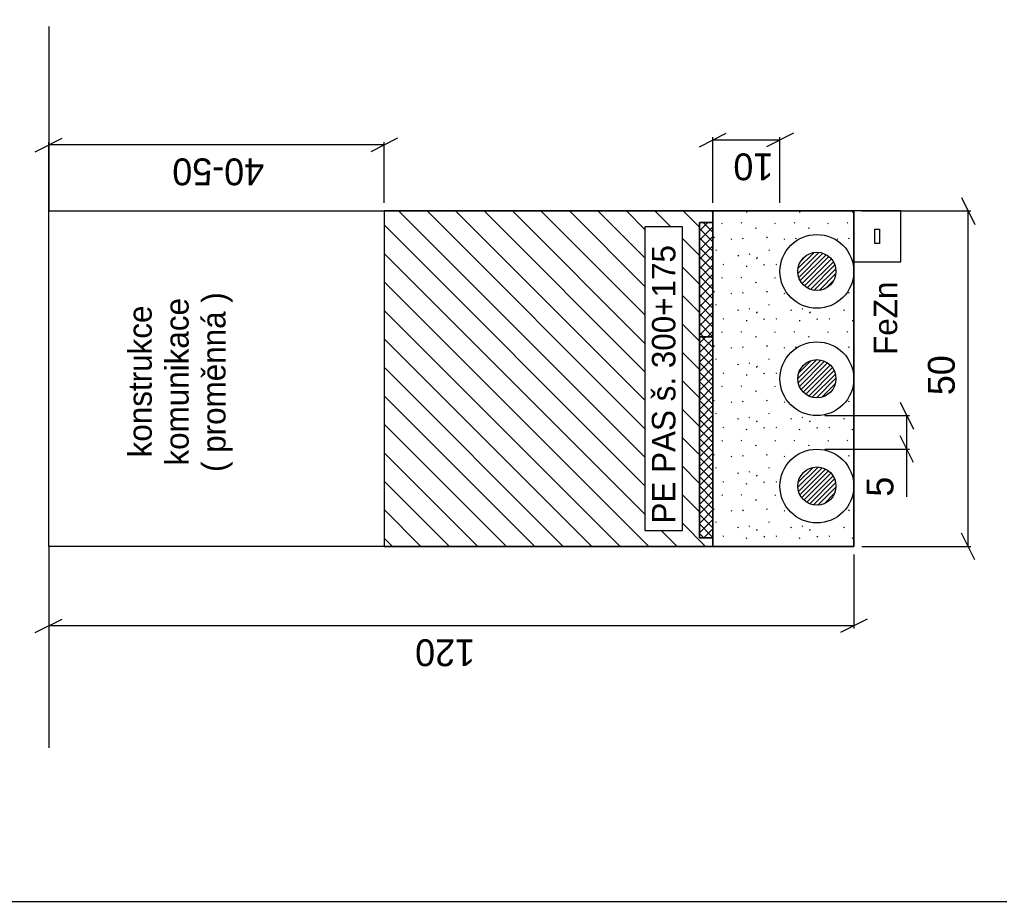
# Model space of a CAD drawing. Extents: x -762592 to -762444, y -1032635 to -1032425.
# Drawn here: x -762577.86 to -762554.5, y -1032634.69 to -1032613.66 of the extents above; entities that cross this region are included whole.
import ezdxf

# ---------------------------------------------------------------- set-up
doc = ezdxf.new("R2010")
doc.units = 0
for name, color, linetype in [('Kabeláž - kabelové vedení HDV - stávající', 7, 'Continuous'), ('Tisk', 7, 'Continuous'), ('X ŘEZY TRASOU', 7, 'Continuous'), ('X ŘEZY TRASOU - KÓTY', 7, 'Continuous'), ('X ŘEZY TRASOU - ŠRAFY', 7, 'Continuous')]:
    doc.layers.add(name, color=color, linetype=linetype)

msp = doc.modelspace()

# ---------------------------------------------------------------- linework, layer by layer
at = {"layer": 'Kabeláž - kabelové vedení HDV - stávající'}
for p, q in [((-762559.301, -1032619.71), (-762558.799, -1032619.208)), ((-762559.299, -1032619.596), (-762558.913, -1032619.21)), ((-762559.281, -1032619.803), (-762558.705, -1032619.228)), ((-762559.246, -1032619.882), (-762558.627, -1032619.263)), ((-762559.231, -1032619.414), (-762559.095, -1032619.278)), ((-762559.201, -1032619.95), (-762558.56, -1032619.309)), ((-762559.145, -1032620.006), (-762558.502, -1032619.364)), ((-762559.079, -1032620.054), (-762558.456, -1032619.431)), ((-762559.002, -1032620.09), (-762558.42, -1032619.508)), ((-762558.91, -1032620.112), (-762558.398, -1032619.599)), ((-762558.798, -1032620.113), (-762558.396, -1032619.711)), ((-762558.635, -1032620.062), (-762558.446, -1032619.873)), ((-762559.304, -1032622.216), (-762558.853, -1032621.765)), ((-762559.293, -1032622.319), (-762558.751, -1032621.776)), ((-762559.282, -1032622.081), (-762558.988, -1032621.788)), ((-762559.266, -1032622.405), (-762558.665, -1032621.804)), ((-762559.225, -1032622.477), (-762558.592, -1032621.844)), ((-762559.174, -1032622.539), (-762558.53, -1032621.895)), ((-762559.114, -1032622.592), (-762558.478, -1032621.956)), ((-762559.042, -1032622.633), (-762558.436, -1032622.027)), ((-762558.958, -1032622.663), (-762558.407, -1032622.111)), ((-762558.858, -1032622.676), (-762558.394, -1032622.211)), ((-762558.729, -1032622.66), (-762558.41, -1032622.34)), ((-762559.303, -1032624.81), (-762558.819, -1032624.326)), ((-762559.294, -1032624.688), (-762558.941, -1032624.335)), ((-762559.287, -1032624.907), (-762558.723, -1032624.343)), ((-762559.254, -1032624.988), (-762558.641, -1032624.375)), ((-762559.21, -1032625.057), (-762558.572, -1032624.419)), ((-762559.157, -1032625.116), (-762558.513, -1032624.473)), ((-762559.092, -1032625.165), (-762558.464, -1032624.537)), ((-762559.018, -1032625.204), (-762558.426, -1032624.612)), ((-762558.929, -1032625.229), (-762558.4, -1032624.699)), ((-762558.823, -1032625.235), (-762558.394, -1032624.806)), ((-762558.676, -1032625.202), (-762558.427, -1032624.953))]:
    msp.add_line(p, q, dxfattribs=at)
at = {"layer": 'Tisk'}
msp.add_lwpolyline([(-762589.528, -1032529.685), (-762592.028, -1032529.685), (-762592.028, -1032634.685), (-762443.528, -1032634.685), (-762443.528, -1032529.685), (-762446.028, -1032529.685)], dxfattribs=at)
at = {"layer": 'X ŘEZY TRASOU'}
for p, q in [((-762577.169, -1032613.821), (-762577.169, -1032618.221)), ((-762577.169, -1032626.221), (-762577.169, -1032618.221)), ((-762577.169, -1032618.221), (-762561.329, -1032618.221)), ((-762569.169, -1032618.221), (-762569.169, -1032626.221)), ((-762561.329, -1032618.221), (-762561.329, -1032626.221)), ((-762561.329, -1032626.221), (-762561.329, -1032618.221)), ((-762561.329, -1032618.221), (-762557.969, -1032618.221)), ((-762557.969, -1032618.221), (-762557.969, -1032619.43)), ((-762556.847, -1032618.221), (-762557.969, -1032618.221)), ((-762557.969, -1032618.221), (-762557.969, -1032626.221)), ((-762556.847, -1032619.43), (-762556.847, -1032618.221)), ((-762561.329, -1032618.498), (-762561.649, -1032618.498)), ((-762561.649, -1032618.498), (-762561.649, -1032621.218)), ((-762561.649, -1032618.694), (-762561.453, -1032618.498)), ((-762561.329, -1032618.498), (-762561.649, -1032618.498)), ((-762561.649, -1032618.498), (-762561.649, -1032621.218)), ((-762561.649, -1032618.92), (-762561.329, -1032618.6)), ((-762561.329, -1032618.729), (-762561.56, -1032618.498)), ((-762561.329, -1032618.502), (-762561.334, -1032618.498)), ((-762561.329, -1032621.218), (-762561.329, -1032618.498)), ((-762561.329, -1032621.218), (-762561.329, -1032618.498)), ((-762561.329, -1032618.955), (-762561.649, -1032618.635)), ((-762561.649, -1032619.146), (-762561.329, -1032618.826)), ((-762557.463, -1032618.997), (-762557.463, -1032618.654)), ((-762557.463, -1032618.654), (-762557.352, -1032618.654)), ((-762557.352, -1032618.654), (-762557.352, -1032618.997)), ((-762561.329, -1032619.181), (-762561.649, -1032618.861)), ((-762561.649, -1032619.373), (-762561.329, -1032619.053)), ((-762557.352, -1032618.997), (-762557.463, -1032618.997)), ((-762561.329, -1032619.408), (-762561.649, -1032619.088)), ((-762561.649, -1032619.599), (-762561.329, -1032619.279)), ((-762561.329, -1032619.634), (-762561.649, -1032619.314)), ((-762561.649, -1032619.825), (-762561.329, -1032619.505)), ((-762561.329, -1032619.86), (-762561.649, -1032619.54)), ((-762557.969, -1032619.43), (-762556.847, -1032619.43)), ((-762561.649, -1032620.051), (-762561.329, -1032619.731)), ((-762561.329, -1032620.086), (-762561.649, -1032619.766)), ((-762561.649, -1032620.278), (-762561.329, -1032619.958)), ((-762561.329, -1032620.313), (-762561.649, -1032619.993)), ((-762561.649, -1032620.504), (-762561.329, -1032620.184)), ((-762561.329, -1032620.539), (-762561.649, -1032620.219)), ((-762561.649, -1032620.73), (-762561.329, -1032620.41)), ((-762561.329, -1032620.765), (-762561.649, -1032620.445)), ((-762561.649, -1032620.956), (-762561.329, -1032620.636)), ((-762561.329, -1032620.992), (-762561.649, -1032620.672)), ((-762561.649, -1032621.183), (-762561.329, -1032620.863)), ((-762561.329, -1032621.218), (-762561.649, -1032620.898)), ((-762561.555, -1032621.218), (-762561.649, -1032621.124)), ((-762561.457, -1032621.218), (-762561.329, -1032621.089)), ((-762561.649, -1032626.018), (-762561.649, -1032621.218)), ((-762561.649, -1032621.218), (-762561.329, -1032621.218)), ((-762561.649, -1032621.372), (-762561.495, -1032621.218)), ((-762561.649, -1032621.218), (-762561.329, -1032621.218)), ((-762561.329, -1032621.218), (-762561.649, -1032621.218)), ((-762561.649, -1032621.218), (-762561.649, -1032626.018)), ((-762561.649, -1032621.218), (-762561.329, -1032621.218)), ((-762561.649, -1032621.598), (-762561.329, -1032621.278)), ((-762561.329, -1032621.704), (-762561.649, -1032621.384)), ((-762561.329, -1032621.478), (-762561.589, -1032621.218)), ((-762561.329, -1032621.252), (-762561.363, -1032621.218)), ((-762561.329, -1032621.218), (-762561.329, -1032626.018)), ((-762561.329, -1032626.018), (-762561.329, -1032621.218)), ((-762561.649, -1032621.824), (-762561.329, -1032621.504)), ((-762561.329, -1032621.931), (-762561.649, -1032621.611)), ((-762561.649, -1032622.051), (-762561.329, -1032621.731)), ((-762561.329, -1032622.157), (-762561.649, -1032621.837)), ((-762561.649, -1032622.277), (-762561.329, -1032621.957)), ((-762561.329, -1032622.383), (-762561.649, -1032622.063)), ((-762561.649, -1032622.503), (-762561.329, -1032622.183)), ((-762561.329, -1032622.61), (-762561.649, -1032622.29)), ((-762561.649, -1032622.729), (-762561.329, -1032622.409)), ((-762561.329, -1032622.836), (-762561.649, -1032622.516)), ((-762561.649, -1032622.956), (-762561.329, -1032622.636)), ((-762561.329, -1032623.062), (-762561.649, -1032622.742)), ((-762561.649, -1032623.182), (-762561.329, -1032622.862)), ((-762561.329, -1032623.288), (-762561.649, -1032622.968)), ((-762561.649, -1032623.408), (-762561.329, -1032623.088)), ((-762561.329, -1032623.515), (-762561.649, -1032623.195)), ((-762561.649, -1032623.634), (-762561.329, -1032623.314)), ((-762561.329, -1032623.741), (-762561.649, -1032623.421)), ((-762561.649, -1032623.861), (-762561.329, -1032623.541)), ((-762561.329, -1032623.967), (-762561.649, -1032623.647)), ((-762561.649, -1032624.087), (-762561.329, -1032623.767)), ((-762561.329, -1032624.193), (-762561.649, -1032623.873)), ((-762561.649, -1032624.313), (-762561.329, -1032623.993)), ((-762561.329, -1032624.42), (-762561.649, -1032624.1)), ((-762561.649, -1032624.54), (-762561.329, -1032624.22)), ((-762561.329, -1032624.646), (-762561.649, -1032624.326)), ((-762561.649, -1032624.766), (-762561.329, -1032624.446)), ((-762561.329, -1032624.872), (-762561.649, -1032624.552)), ((-762561.649, -1032624.992), (-762561.329, -1032624.672)), ((-762561.329, -1032625.099), (-762561.649, -1032624.779)), ((-762561.649, -1032625.218), (-762561.329, -1032624.898)), ((-762561.329, -1032625.325), (-762561.649, -1032625.005)), ((-762561.649, -1032625.445), (-762561.329, -1032625.125)), ((-762561.329, -1032625.551), (-762561.649, -1032625.231)), ((-762561.649, -1032625.671), (-762561.329, -1032625.351)), ((-762561.329, -1032625.777), (-762561.649, -1032625.457)), ((-762561.649, -1032625.897), (-762561.329, -1032625.577)), ((-762561.329, -1032626.004), (-762561.649, -1032625.684)), ((-762561.543, -1032626.018), (-762561.329, -1032625.804)), ((-762561.541, -1032626.018), (-762561.649, -1032625.91)), ((-762561.329, -1032626.018), (-762561.649, -1032626.018)), ((-762561.649, -1032626.018), (-762561.329, -1032626.018)), ((-762577.169, -1032626.221), (-762577.169, -1032631.021)), ((-762561.329, -1032626.221), (-762577.169, -1032626.221)), ((-762557.969, -1032626.221), (-762561.329, -1032626.221)), ((-762577.169, -1032627.821), (-762577.169, -1032630.115))]:
    msp.add_line(p, q, dxfattribs=at)
for centre, radius in [((-762558.849, -1032619.661), 0.88), ((-762558.849, -1032619.661), 0.456), ((-762558.849, -1032622.221), 0.88), ((-762558.849, -1032622.221), 0.456), ((-762558.849, -1032624.781), 0.88), ((-762558.849, -1032624.781), 0.456)]:
    msp.add_circle(centre, radius, dxfattribs=at)
at = {"layer": 'X ŘEZY TRASOU - KÓTY'}
for p, q in [((-762577.489, -1032616.807), (-762576.849, -1032616.487)), ((-762568.849, -1032616.487), (-762569.489, -1032616.807)), ((-762561.649, -1032616.687), (-762561.009, -1032616.367)), ((-762561.329, -1032618.029), (-762561.329, -1032616.463)), ((-762559.409, -1032616.367), (-762560.049, -1032616.687)), ((-762559.729, -1032618.029), (-762559.729, -1032616.463)), ((-762577.169, -1032618.221), (-762577.169, -1032616.583)), ((-762569.169, -1032616.647), (-762577.169, -1032616.647)), ((-762569.169, -1032618.029), (-762569.169, -1032616.583)), ((-762561.329, -1032616.527), (-762559.729, -1032616.527)), ((-762555.401, -1032617.901), (-762555.081, -1032618.541)), ((-762557.777, -1032618.221), (-762555.177, -1032618.221)), ((-762555.241, -1032626.221), (-762555.241, -1032618.221)), ((-762556.864, -1032622.781), (-762556.544, -1032623.421)), ((-762558.657, -1032623.101), (-762556.64, -1032623.101)), ((-762556.704, -1032623.901), (-762556.704, -1032623.101)), ((-762556.544, -1032624.221), (-762556.864, -1032623.581)), ((-762558.657, -1032623.901), (-762556.64, -1032623.901)), ((-762556.704, -1032625.034), (-762556.704, -1032623.901)), ((-762555.081, -1032626.541), (-762555.401, -1032625.901)), ((-762557.777, -1032626.221), (-762555.177, -1032626.221)), ((-762577.169, -1032626.413), (-762577.169, -1032628.179)), ((-762557.969, -1032626.413), (-762557.969, -1032628.179)), ((-762577.489, -1032628.275), (-762576.849, -1032627.955)), ((-762557.649, -1032627.955), (-762558.289, -1032628.275)), ((-762557.969, -1032628.115), (-762577.169, -1032628.115))]:
    msp.add_line(p, q, dxfattribs=at)
at = {"layer": 'X ŘEZY TRASOU - ŠRAFY'}
for p, q in [((-762569.169, -1032618.221), (-762569.169, -1032626.221)), ((-762562.951, -1032624.093), (-762568.824, -1032618.221)), ((-762562.951, -1032623.414), (-762568.145, -1032618.221)), ((-762562.951, -1032622.735), (-762567.466, -1032618.221)), ((-762562.951, -1032622.056), (-762566.787, -1032618.221)), ((-762562.951, -1032621.378), (-762566.108, -1032618.221)), ((-762562.951, -1032620.699), (-762565.429, -1032618.221)), ((-762562.951, -1032620.02), (-762564.751, -1032618.221)), ((-762562.951, -1032619.341), (-762564.072, -1032618.221)), ((-762562.951, -1032618.662), (-762563.393, -1032618.221)), ((-762562.335, -1032618.6), (-762562.714, -1032618.221)), ((-762561.649, -1032618.607), (-762562.035, -1032618.221)), ((-762561.329, -1032618.249), (-762561.357, -1032618.221)), ((-762557.969, -1032618.221), (-762561.329, -1032618.221)), ((-762561.329, -1032618.221), (-762561.329, -1032618.498)), ((-762560.533, -1032618.241), (-762560.509, -1032618.239)), ((-762559.269, -1032618.241), (-762559.244, -1032618.239)), ((-762558.004, -1032618.241), (-762557.98, -1032618.239)), ((-762557.969, -1032619.43), (-762557.969, -1032618.221)), ((-762562.951, -1032624.772), (-762569.169, -1032618.554)), ((-762562.055, -1032618.6), (-762562.951, -1032618.6)), ((-762562.951, -1032618.6), (-762562.951, -1032625.842)), ((-762562.055, -1032625.842), (-762562.055, -1032618.6)), ((-762561.649, -1032621.218), (-762561.649, -1032618.498)), ((-762561.649, -1032618.498), (-762561.329, -1032618.498)), ((-762561.329, -1032618.498), (-762561.329, -1032621.218)), ((-762561.115, -1032618.52), (-762561.099, -1032618.509)), ((-762560.653, -1032618.509), (-762560.637, -1032618.499)), ((-762559.851, -1032618.52), (-762559.835, -1032618.509)), ((-762559.389, -1032618.509), (-762559.373, -1032618.499)), ((-762558.587, -1032618.52), (-762558.57, -1032618.509)), ((-762558.125, -1032618.509), (-762558.108, -1032618.499)), ((-762561.288, -1032618.858), (-762561.313, -1032618.847)), ((-762560.287, -1032618.639), (-762560.311, -1032618.628)), ((-762560.024, -1032618.858), (-762560.048, -1032618.847)), ((-762559.023, -1032618.639), (-762559.047, -1032618.628)), ((-762561.649, -1032619.286), (-762562.055, -1032618.879)), ((-762560.894, -1032618.894), (-762560.877, -1032618.883)), ((-762560.601, -1032618.885), (-762560.625, -1032618.874)), ((-762559.629, -1032618.894), (-762559.613, -1032618.883)), ((-762559.337, -1032618.885), (-762559.361, -1032618.874)), ((-762558.365, -1032618.894), (-762558.349, -1032618.883)), ((-762558.072, -1032618.885), (-762558.097, -1032618.874)), ((-762562.951, -1032625.45), (-762569.169, -1032619.233)), ((-762561.257, -1032619.161), (-762561.241, -1032619.15)), ((-762560.712, -1032619.296), (-762560.736, -1032619.286)), ((-762560.461, -1032619.257), (-762560.445, -1032619.246)), ((-762559.992, -1032619.161), (-762559.976, -1032619.15)), ((-762561.086, -1032619.496), (-762561.07, -1032619.485)), ((-762560.533, -1032619.538), (-762560.509, -1032619.535)), ((-762560.287, -1032619.353), (-762560.271, -1032619.342)), ((-762560.281, -1032619.342), (-762560.265, -1032619.332)), ((-762560.086, -1032619.513), (-762560.111, -1032619.502)), ((-762559.822, -1032619.496), (-762559.805, -1032619.485)), ((-762557.969, -1032624.781), (-762557.969, -1032619.43)), ((-762561.649, -1032619.965), (-762562.055, -1032619.558)), ((-762562.86, -1032626.221), (-762569.169, -1032619.912)), ((-762561.115, -1032619.816), (-762561.099, -1032619.805)), ((-762560.653, -1032619.806), (-762560.637, -1032619.795)), ((-762560.287, -1032619.935), (-762560.311, -1032619.924)), ((-762559.851, -1032619.816), (-762559.835, -1032619.805)), ((-762561.649, -1032620.644), (-762562.055, -1032620.237)), ((-762561.288, -1032620.154), (-762561.313, -1032620.144)), ((-762560.894, -1032620.19), (-762560.877, -1032620.18)), ((-762560.601, -1032620.182), (-762560.625, -1032620.171)), ((-762560.024, -1032620.154), (-762560.048, -1032620.144)), ((-762559.629, -1032620.19), (-762559.613, -1032620.18)), ((-762558.072, -1032620.182), (-762558.097, -1032620.171)), ((-762561.257, -1032620.457), (-762561.241, -1032620.447)), ((-762559.992, -1032620.457), (-762559.976, -1032620.447)), ((-762563.539, -1032626.221), (-762569.169, -1032620.591)), ((-762560.712, -1032620.593), (-762560.736, -1032620.582)), ((-762560.461, -1032620.554), (-762560.445, -1032620.543)), ((-762560.287, -1032620.65), (-762560.271, -1032620.639)), ((-762560.281, -1032620.639), (-762560.265, -1032620.628)), ((-762559.448, -1032620.593), (-762559.472, -1032620.582)), ((-762559.197, -1032620.554), (-762559.181, -1032620.543)), ((-762559.023, -1032620.65), (-762559.006, -1032620.639)), ((-762559.016, -1032620.639), (-762559, -1032620.628)), ((-762558.183, -1032620.593), (-762558.208, -1032620.582)), ((-762561.649, -1032621.323), (-762562.055, -1032620.916)), ((-762561.086, -1032620.793), (-762561.07, -1032620.782)), ((-762560.533, -1032620.835), (-762560.509, -1032620.832)), ((-762560.086, -1032620.81), (-762560.111, -1032620.799)), ((-762559.822, -1032620.793), (-762559.805, -1032620.782)), ((-762559.269, -1032620.835), (-762559.244, -1032620.832)), ((-762558.822, -1032620.81), (-762558.846, -1032620.799)), ((-762558.557, -1032620.793), (-762558.541, -1032620.782)), ((-762558.004, -1032620.835), (-762557.98, -1032620.832)), ((-762561.115, -1032621.113), (-762561.099, -1032621.102)), ((-762560.653, -1032621.102), (-762560.637, -1032621.092)), ((-762559.851, -1032621.113), (-762559.835, -1032621.102)), ((-762559.389, -1032621.102), (-762559.373, -1032621.092)), ((-762558.587, -1032621.113), (-762558.57, -1032621.102)), ((-762558.125, -1032621.102), (-762558.108, -1032621.092)), ((-762564.218, -1032626.221), (-762569.169, -1032621.27)), ((-762561.329, -1032621.218), (-762561.329, -1032626.018)), ((-762560.287, -1032621.232), (-762560.311, -1032621.221)), ((-762559.023, -1032621.232), (-762559.047, -1032621.221)), ((-762561.649, -1032622.001), (-762562.055, -1032621.595)), ((-762561.288, -1032621.451), (-762561.313, -1032621.44)), ((-762560.894, -1032621.487), (-762560.877, -1032621.476)), ((-762560.601, -1032621.478), (-762560.625, -1032621.467)), ((-762560.024, -1032621.451), (-762560.048, -1032621.44)), ((-762559.629, -1032621.487), (-762559.613, -1032621.476)), ((-762559.337, -1032621.478), (-762559.361, -1032621.467)), ((-762558.364, -1032621.486), (-762558.349, -1032621.476)), ((-762558.072, -1032621.478), (-762558.097, -1032621.467)), ((-762561.257, -1032621.754), (-762561.241, -1032621.743)), ((-762560.712, -1032621.889), (-762560.736, -1032621.879)), ((-762560.461, -1032621.85), (-762560.445, -1032621.839)), ((-762559.992, -1032621.754), (-762559.976, -1032621.743)), ((-762564.896, -1032626.221), (-762569.169, -1032621.949)), ((-762561.086, -1032622.089), (-762561.07, -1032622.078)), ((-762560.287, -1032621.946), (-762560.271, -1032621.936)), ((-762560.281, -1032621.936), (-762560.265, -1032621.925)), ((-762560.086, -1032622.106), (-762560.111, -1032622.095)), ((-762559.822, -1032622.089), (-762559.805, -1032622.078)), ((-762561.649, -1032622.68), (-762562.055, -1032622.274)), ((-762560.533, -1032622.131), (-762560.509, -1032622.128)), ((-762561.115, -1032622.409), (-762561.099, -1032622.398)), ((-762560.653, -1032622.399), (-762560.637, -1032622.388)), ((-762560.287, -1032622.528), (-762560.311, -1032622.517)), ((-762559.851, -1032622.409), (-762559.835, -1032622.398)), ((-762565.575, -1032626.221), (-762569.169, -1032622.627)), ((-762561.288, -1032622.748), (-762561.313, -1032622.737)), ((-762560.894, -1032622.784), (-762560.877, -1032622.773)), ((-762560.601, -1032622.775), (-762560.625, -1032622.764)), ((-762560.024, -1032622.748), (-762560.048, -1032622.737)), ((-762559.629, -1032622.784), (-762559.613, -1032622.773)), ((-762558.072, -1032622.775), (-762558.097, -1032622.764)), ((-762561.649, -1032623.359), (-762562.055, -1032622.952)), ((-762561.257, -1032623.05), (-762561.241, -1032623.04)), ((-762559.992, -1032623.05), (-762559.976, -1032623.04)), ((-762560.712, -1032623.186), (-762560.736, -1032623.175)), ((-762560.461, -1032623.147), (-762560.445, -1032623.136)), ((-762560.287, -1032623.243), (-762560.271, -1032623.232)), ((-762560.281, -1032623.232), (-762560.265, -1032623.221)), ((-762559.448, -1032623.186), (-762559.472, -1032623.175)), ((-762559.197, -1032623.147), (-762559.181, -1032623.136)), ((-762559.023, -1032623.243), (-762559.006, -1032623.232)), ((-762559.016, -1032623.232), (-762559, -1032623.221)), ((-762558.183, -1032623.186), (-762558.208, -1032623.175)), ((-762566.254, -1032626.221), (-762569.169, -1032623.306)), ((-762561.086, -1032623.386), (-762561.07, -1032623.375)), ((-762560.533, -1032623.428), (-762560.509, -1032623.425)), ((-762560.086, -1032623.403), (-762560.111, -1032623.392)), ((-762559.822, -1032623.386), (-762559.805, -1032623.375)), ((-762559.269, -1032623.428), (-762559.244, -1032623.425)), ((-762558.822, -1032623.403), (-762558.846, -1032623.392)), ((-762558.557, -1032623.386), (-762558.541, -1032623.375)), ((-762558.004, -1032623.428), (-762557.98, -1032623.425)), ((-762561.649, -1032624.038), (-762562.055, -1032623.631)), ((-762561.115, -1032623.706), (-762561.099, -1032623.695)), ((-762560.653, -1032623.696), (-762560.637, -1032623.685)), ((-762559.851, -1032623.706), (-762559.835, -1032623.695)), ((-762559.389, -1032623.696), (-762559.373, -1032623.685)), ((-762558.587, -1032623.706), (-762558.57, -1032623.695)), ((-762558.125, -1032623.696), (-762558.108, -1032623.685)), ((-762566.933, -1032626.221), (-762569.169, -1032623.985)), ((-762560.287, -1032623.825), (-762560.311, -1032623.814)), ((-762559.023, -1032623.825), (-762559.047, -1032623.814)), ((-762561.288, -1032624.044), (-762561.313, -1032624.033)), ((-762560.894, -1032624.08), (-762560.877, -1032624.069)), ((-762560.601, -1032624.071), (-762560.625, -1032624.06)), ((-762560.024, -1032624.044), (-762560.048, -1032624.033)), ((-762559.629, -1032624.08), (-762559.613, -1032624.069)), ((-762559.356, -1032624.062), (-762559.361, -1032624.06)), ((-762558.072, -1032624.071), (-762558.097, -1032624.06)), ((-762561.649, -1032624.717), (-762562.055, -1032624.31)), ((-762561.257, -1032624.347), (-762561.241, -1032624.336)), ((-762560.461, -1032624.443), (-762560.445, -1032624.432)), ((-762559.992, -1032624.347), (-762559.976, -1032624.336)), ((-762567.612, -1032626.221), (-762569.169, -1032624.664)), ((-762561.086, -1032624.682), (-762561.07, -1032624.672)), ((-762560.712, -1032624.483), (-762560.736, -1032624.472)), ((-762560.287, -1032624.539), (-762560.271, -1032624.529)), ((-762560.281, -1032624.529), (-762560.265, -1032624.518)), ((-762560.086, -1032624.699), (-762560.111, -1032624.688)), ((-762559.822, -1032624.682), (-762559.805, -1032624.672)), ((-762560.533, -1032624.724), (-762560.509, -1032624.721)), ((-762561.649, -1032625.396), (-762562.055, -1032624.989)), ((-762561.115, -1032625.002), (-762561.099, -1032624.991)), ((-762560.653, -1032624.992), (-762560.637, -1032624.981)), ((-762560.287, -1032625.121), (-762560.311, -1032625.111)), ((-762559.851, -1032625.002), (-762559.835, -1032624.991)), ((-762568.291, -1032626.221), (-762569.169, -1032625.343)), ((-762561.288, -1032625.341), (-762561.313, -1032625.33)), ((-762560.894, -1032625.377), (-762560.877, -1032625.366)), ((-762560.601, -1032625.368), (-762560.625, -1032625.357)), ((-762560.024, -1032625.341), (-762560.048, -1032625.33)), ((-762559.629, -1032625.377), (-762559.613, -1032625.366)), ((-762558.072, -1032625.368), (-762558.097, -1032625.357)), ((-762562.951, -1032625.842), (-762562.055, -1032625.842)), ((-762562.181, -1032626.221), (-762562.56, -1032625.842)), ((-762561.502, -1032626.221), (-762562.055, -1032625.668)), ((-762561.257, -1032625.644), (-762561.241, -1032625.633)), ((-762560.712, -1032625.779), (-762560.736, -1032625.768)), ((-762560.461, -1032625.74), (-762560.445, -1032625.729)), ((-762560.287, -1032625.836), (-762560.271, -1032625.825)), ((-762560.281, -1032625.825), (-762560.265, -1032625.814)), ((-762559.992, -1032625.644), (-762559.976, -1032625.633)), ((-762559.448, -1032625.779), (-762559.472, -1032625.768)), ((-762559.197, -1032625.74), (-762559.181, -1032625.729)), ((-762559.023, -1032625.836), (-762559.006, -1032625.825)), ((-762559.016, -1032625.825), (-762559, -1032625.814)), ((-762558.183, -1032625.779), (-762558.208, -1032625.768)), ((-762568.969, -1032626.221), (-762569.169, -1032626.021)), ((-762561.329, -1032626.221), (-762561.329, -1032626.018)), ((-762561.329, -1032626.018), (-762561.329, -1032626.221)), ((-762561.086, -1032625.979), (-762561.07, -1032625.968)), ((-762560.533, -1032626.021), (-762560.509, -1032626.018)), ((-762560.086, -1032625.996), (-762560.111, -1032625.985)), ((-762559.822, -1032625.979), (-762559.805, -1032625.968)), ((-762559.269, -1032626.021), (-762559.244, -1032626.018)), ((-762558.822, -1032625.996), (-762558.846, -1032625.985)), ((-762558.557, -1032625.979), (-762558.541, -1032625.968)), ((-762558.004, -1032626.021), (-762557.98, -1032626.018)), ((-762569.169, -1032626.221), (-762561.329, -1032626.221))]:
    msp.add_line(p, q, dxfattribs=at)
for points in [[(-762561.329, -1032618.498), (-762561.329, -1032618.221), (-762569.169, -1032618.221)], [(-762561.329, -1032626.018), (-762561.649, -1032626.018), (-762561.649, -1032621.218)], [(-762561.329, -1032626.221), (-762557.969, -1032626.221), (-762557.969, -1032624.781)]]:
    msp.add_lwpolyline(points, dxfattribs=at)
for centre in [(-762558.849, -1032619.661), (-762558.849, -1032622.221), (-762558.849, -1032624.781)]:
    msp.add_circle(centre, 0.88, dxfattribs=at)

# ---------------------------------------------------------------- texts
at = {"layer": 'X ŘEZY TRASOU'}
for s, p in [('PE PAS š. 300+175', (-762562.223, -1032625.674)), ('FeZn', (-762556.933, -1032621.653)), ('( proměnná )', (-762572.953, -1032624.445)), ('komunikace', (-762573.833, -1032624.292)), ('konstrukce', (-762574.713, -1032624.096))]:
    msp.add_text(s, height=0.56, rotation=90, dxfattribs=at).set_placement(p)
at = {"layer": 'X ŘEZY TRASOU - KÓTY'}
for s, rotation, p in [('40-50', 180, (-762572.033, -1032616.967)), ('10', 180, (-762559.888, -1032616.847)), ('50', 90, (-762555.561, -1032622.613)), ('5', 90, (-762557.024, -1032625.034)), ('120', 180, (-762567.003, -1032628.435))]:
    msp.add_text(s, height=0.64, rotation=rotation, dxfattribs=at).set_placement(p)

doc.saveas('drawing.dxf')
